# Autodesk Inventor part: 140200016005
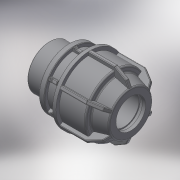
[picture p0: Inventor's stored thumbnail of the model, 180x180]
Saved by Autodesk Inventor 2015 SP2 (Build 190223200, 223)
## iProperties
Created: 2017-08
Part Number: 140200016005
Material: Generic
Description: PLASSON L.14 MALE ADAPTOR (SILVER) 16-1/2''
Document SubType Name: Modeling
Designer: KIM
Density: 1 g/cm^3
Appearance: Default
Author: KIM
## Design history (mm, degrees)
derived "140200.ipt"
feature "Solid1::140200.ipt"
tag "TaggingFeature1"
body "Solid1"
other parameters: "d1" = 16, "d2" = 59, "d4" = 15 deg, "d5" = 38.94, "d6" = 12.8502, "d10" = 39, "d16" = 16.32, "d17" = 2.95, "d18" = 79, "d19" = 4.8, "d21" = 4.8, "d22" = 25.146, "d24" = 2.95, "d25" = 35.1, "d26" = 29.25, "d27" = 2.95, "d28" = 135 deg, "d29" = 1.77, "d31" = 0.8, "d44" = 0.32, "d45" = 0.48, "d46" = 150 deg, "d49" = 1.95, "d50" = 0, "d51" = 1.17, "d52" = 0.78, "d53" = 45 deg, "d54" = 21, "d55" = 8.4, "d56" = 1.95, "d57" = 0, "d58" = 0.48, "d59" = 0.32, "d61" = 360 deg, "d63" = 20.955, "d64" = 12.8, "d65" = 16, "d66" = 28.28925, "d_" = 16, "R_" = 20.955, "E_" = 39, "H_" = 79, "l_" = 59, "l_2" = 16
